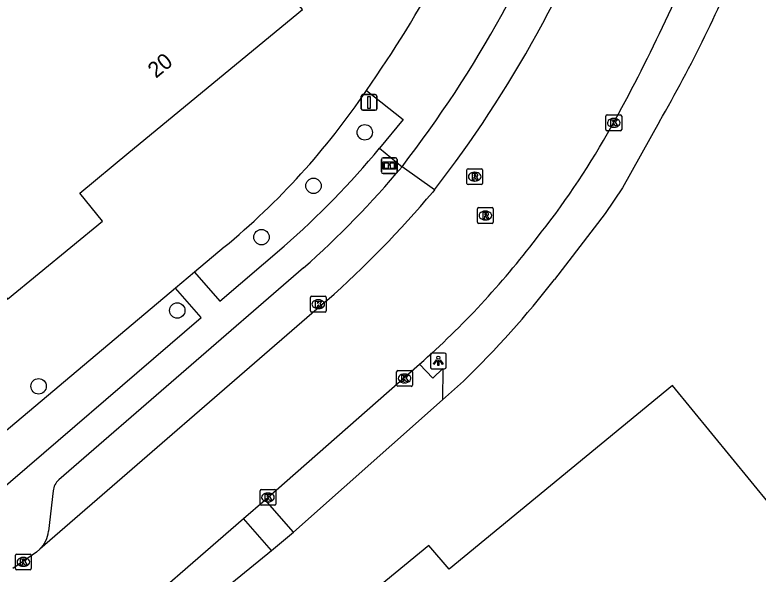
# Model space of a CAD drawing. Extents: x 156651 to 158072, y 387631 to 388990.
# Drawn here: x 157266.5 to 157313.66, y 387776.09 to 387811.56 of the extents above; entities that cross this region are included whole.
import ezdxf

# ---------------------------------------------------------------- set-up
doc = ezdxf.new("R2010")
doc.units = 0
for name, color, linetype in [('IMGEO_Boom', 7, 'Continuous'), ('IMGEO_Groenvoorziening', 7, 'Continuous'), ('IMGEO_Informatiebord', 7, 'Continuous'), ('IMGEO_Kolk', 7, 'Continuous'), ('IMGEO_Lichtpunt', 7, 'Continuous'), ('IMGEO_Pand', 7, 'Continuous'), ('IMGEO_Pand_nummerreeks', 7, 'Continuous'), ('IMGEO_Rijbaan_lokaal_gesloten', 7, 'Continuous'), ('IMGEO_Rioolput', 7, 'Continuous'), ('IMGEO_Verkeersbordpaal', 7, 'Continuous'), ('IMGEO_Voetpad_open', 7, 'Continuous')]:
    doc.layers.add(name, color=color, linetype=linetype)

msp = doc.modelspace()

# ---------------------------------------------------------------- linework, layer by layer
at = {"layer": 'IMGEO_Boom'}
for centre in [(157288.701, 387804.11), (157285.448, 387800.716), (157282.148, 387797.464), (157276.803, 387792.806), (157268.007, 387788.001)]:
    msp.add_circle(centre, 0.489, dxfattribs=at)
at = {"layer": 'IMGEO_Groenvoorziening'}
for points in [[(157279.77, 387796.82), (157277.903, 387795.246)], [(157276.702, 387794.234), (157265.834, 387785.07)], [(157293.629, 387787.152), (157284.18, 387778.754)], [(157273.993, 387770.42), (157282.784, 387777.576)]]:
    msp.add_lwpolyline(points, dxfattribs=at)
msp.add_arc((157249.773, 387833.157), 47.119, 309.5398, 325.9461, dxfattribs=at)
at = {"layer": 'IMGEO_Informatiebord'}
for p, q in [((157289.862, 387802.498), (157290.652, 387802.498)), ((157290.652, 387802.498), (157289.862, 387802.498)), ((157289.762, 387801.598), (157289.762, 387802.398)), ((157289.762, 387802.398), (157289.762, 387801.598)), ((157290.752, 387802.398), (157290.752, 387801.598)), ((157290.752, 387801.598), (157290.752, 387802.398)), ((157290.652, 387801.498), (157289.862, 387801.498)), ((157289.862, 387801.498), (157290.652, 387801.498))]:
    msp.add_line(p, q, dxfattribs=at)
for points in [[(157289.863, 387802.23), (157290.651, 387802.23), (157290.651, 387801.766), (157289.863, 387801.766), (157289.863, 387802.23)], [(157289.928, 387802.165), (157289.928, 387801.831), (157290.203, 387801.831), (157290.204, 387802.044), (157290.308, 387802.045), (157290.309, 387801.831), (157290.586, 387801.831), (157290.586, 387802.165), (157290.31, 387802.165), (157290.31, 387802.085), (157290.204, 387802.085), (157290.204, 387802.165), (157289.928, 387802.165)]]:
    msp.add_lwpolyline(points, dxfattribs=at)
for centre, start, end in [((157289.862, 387802.398), 90, 180), ((157289.862, 387802.398), 90, 180), ((157290.652, 387802.398), 0, 90), ((157290.652, 387802.398), 360, 90), ((157289.862, 387801.598), 180, 270), ((157289.862, 387801.598), 180, 270), ((157290.652, 387801.598), 270, 0), ((157290.652, 387801.598), 270, 0)]:
    msp.add_arc(centre, 0.1, start, end, dxfattribs=at)
at = {"layer": 'IMGEO_Kolk'}
for p, q in [((157303.997, 387804.287), (157303.997, 387805.139)), ((157304.072, 387805.213), (157304.924, 387805.213)), ((157304.485, 387804.993), (157304.51, 387804.993)), ((157304.998, 387805.139), (157304.998, 387804.287)), ((157304.508, 387804.433), (157304.483, 387804.433)), ((157304.924, 387804.213), (157304.072, 387804.213)), ((157285.251, 387792.783), (157285.251, 387793.635)), ((157285.326, 387793.709), (157286.178, 387793.709)), ((157286.252, 387793.635), (157286.252, 387792.783)), ((157285.739, 387793.489), (157285.764, 387793.489)), ((157286.178, 387792.709), (157285.326, 387792.709)), ((157285.762, 387792.929), (157285.737, 387792.929)), ((157290.723, 387788.073), (157290.723, 387788.925)), ((157290.798, 387788.999), (157291.65, 387788.999)), ((157291.724, 387788.925), (157291.724, 387788.073)), ((157291.211, 387788.779), (157291.236, 387788.779)), ((157291.65, 387787.999), (157290.798, 387787.999)), ((157291.234, 387788.219), (157291.209, 387788.219)), ((157282.058, 387780.526), (157282.058, 387781.378)), ((157282.133, 387781.452), (157282.985, 387781.452)), ((157283.059, 387781.378), (157283.059, 387780.526)), ((157282.546, 387781.232), (157282.571, 387781.232)), ((157282.985, 387780.452), (157282.133, 387780.452)), ((157282.569, 387780.672), (157282.544, 387780.672)), ((157266.541, 387776.435), (157266.541, 387777.287)), ((157266.616, 387777.361), (157267.468, 387777.361)), ((157267.029, 387777.141), (157267.054, 387777.141)), ((157267.542, 387777.287), (157267.542, 387776.435)), ((157267.052, 387776.581), (157267.027, 387776.581)), ((157267.468, 387776.361), (157266.616, 387776.361))]:
    msp.add_line(p, q, dxfattribs=at)
for points in [[(157303.997, 387804.287), (157303.997, 387805.139)], [(157304.072, 387805.213), (157304.924, 387805.213)], [(157304.318, 387804.913), (157304.441, 387804.913), (157304.441, 387804.762), (157304.571, 387804.913), (157304.735, 387804.913), (157304.589, 387804.762), (157304.742, 387804.513), (157304.59, 387804.513), (157304.505, 387804.677), (157304.441, 387804.61), (157304.441, 387804.513), (157304.318, 387804.513), (157304.318, 387804.913)], [(157304.998, 387805.139), (157304.998, 387804.287)], [(157304.924, 387804.213), (157304.072, 387804.213)], [(157285.251, 387792.783), (157285.251, 387793.635)], [(157285.326, 387793.709), (157286.178, 387793.709)], [(157286.252, 387793.635), (157286.252, 387792.783)], [(157285.572, 387793.409), (157285.695, 387793.409), (157285.695, 387793.258), (157285.825, 387793.409), (157285.989, 387793.409), (157285.843, 387793.258), (157285.996, 387793.009), (157285.844, 387793.009), (157285.759, 387793.173), (157285.695, 387793.106), (157285.695, 387793.009), (157285.572, 387793.009), (157285.572, 387793.409)], [(157286.178, 387792.709), (157285.326, 387792.709)], [(157290.723, 387788.073), (157290.723, 387788.925)], [(157290.798, 387788.999), (157291.65, 387788.999)], [(157291.724, 387788.925), (157291.724, 387788.073)], [(157291.044, 387788.699), (157291.167, 387788.699), (157291.167, 387788.548), (157291.297, 387788.699), (157291.461, 387788.699), (157291.315, 387788.548), (157291.468, 387788.299), (157291.316, 387788.299), (157291.231, 387788.463), (157291.167, 387788.396), (157291.167, 387788.299), (157291.044, 387788.299), (157291.044, 387788.699)], [(157291.65, 387787.999), (157290.798, 387787.999)], [(157282.058, 387780.526), (157282.058, 387781.378)], [(157282.133, 387781.452), (157282.985, 387781.452)], [(157283.059, 387781.378), (157283.059, 387780.526)], [(157282.379, 387781.152), (157282.502, 387781.152), (157282.502, 387781.001), (157282.632, 387781.152), (157282.796, 387781.152), (157282.65, 387781.001), (157282.803, 387780.752), (157282.651, 387780.752), (157282.566, 387780.916), (157282.502, 387780.849), (157282.502, 387780.752), (157282.379, 387780.752), (157282.379, 387781.152)], [(157282.985, 387780.452), (157282.133, 387780.452)], [(157266.541, 387776.435), (157266.541, 387777.287)], [(157266.616, 387777.361), (157267.468, 387777.361)], [(157266.862, 387777.061), (157266.985, 387777.061), (157266.985, 387776.91), (157267.115, 387777.061), (157267.279, 387777.061), (157267.133, 387776.91), (157267.286, 387776.661), (157267.134, 387776.661), (157267.049, 387776.825), (157266.985, 387776.758), (157266.985, 387776.661), (157266.862, 387776.661), (157266.862, 387777.061)], [(157267.542, 387777.287), (157267.542, 387776.435)], [(157267.468, 387776.361), (157266.616, 387776.361)]]:
    msp.add_lwpolyline(points, dxfattribs=at)
for centre, start, end in [((157304.074, 387805.137), 91.552, 178.448), ((157304.074, 387805.137), 91.552, 178.448), ((157304.922, 387805.137), 1.552, 88.448), ((157304.922, 387805.137), 1.552, 88.448), ((157304.074, 387804.289), 181.552, 268.448), ((157304.074, 387804.289), 181.552, 268.448), ((157304.922, 387804.289), 271.552, 358.448), ((157304.922, 387804.289), 271.552, 358.448), ((157285.328, 387793.633), 91.552, 178.448), ((157285.328, 387793.633), 91.552, 178.448), ((157286.176, 387793.633), 1.552, 88.448), ((157286.176, 387793.633), 1.552, 88.448), ((157285.328, 387792.785), 181.552, 268.448), ((157285.328, 387792.785), 181.552, 268.448), ((157286.176, 387792.785), 271.552, 358.448), ((157286.176, 387792.785), 271.552, 358.448), ((157290.8, 387788.923), 91.552, 178.448), ((157290.8, 387788.923), 91.552, 178.448), ((157291.648, 387788.923), 1.552, 88.448), ((157291.648, 387788.923), 1.552, 88.448), ((157290.8, 387788.075), 181.552, 268.448), ((157290.8, 387788.075), 181.552, 268.448), ((157291.648, 387788.075), 271.552, 358.448), ((157291.648, 387788.075), 271.552, 358.448), ((157282.135, 387781.376), 91.552, 178.448), ((157282.135, 387781.376), 91.552, 178.448), ((157282.983, 387781.376), 1.552, 88.448), ((157282.983, 387781.376), 1.552, 88.448), ((157282.135, 387780.528), 181.552, 268.448), ((157282.135, 387780.528), 181.552, 268.448), ((157282.983, 387780.528), 271.552, 358.448), ((157282.983, 387780.528), 271.552, 358.448), ((157266.618, 387777.285), 91.552, 178.448), ((157266.618, 387777.285), 91.552, 178.448), ((157267.466, 387777.285), 1.552, 88.448), ((157267.466, 387777.285), 1.552, 88.448), ((157266.618, 387776.437), 181.552, 268.448), ((157266.618, 387776.437), 181.552, 268.448), ((157267.466, 387776.437), 271.552, 358.448), ((157267.466, 387776.437), 271.552, 358.448)]:
    msp.add_arc(centre, 0.0765, start, end, dxfattribs=at)
for centre, major_axis, ratio, start_param, end_param in [((157304.484, 387804.713), (-0.387, 0.002), 0.722429, 4.712389, 7.853982), ((157304.509, 387804.713), (-0.39, 0.002), 0.717154, 1.570796, 4.712389), ((157285.738, 387793.209), (-0.387, 0.002), 0.722429, 4.712389, 7.853982), ((157285.763, 387793.209), (-0.39, 0.002), 0.717154, 1.570796, 4.712389), ((157291.21, 387788.499), (-0.387, 0.002), 0.722429, 4.712389, 7.853982), ((157291.235, 387788.499), (-0.39, 0.002), 0.717154, 1.570796, 4.712389), ((157282.545, 387780.952), (-0.387, 0.002), 0.722429, 4.712389, 7.853982), ((157282.57, 387780.952), (-0.39, 0.002), 0.717154, 1.570796, 4.712389), ((157267.028, 387776.861), (-0.387, 0.002), 0.722429, 4.712389, 7.853982), ((157267.053, 387776.861), (-0.39, 0.002), 0.717154, 1.570796, 4.712389)]:
    msp.add_ellipse(centre, major_axis=major_axis, ratio=ratio, start_param=start_param, end_param=end_param, dxfattribs=at)
at = {"layer": 'IMGEO_Lichtpunt'}
for p, q in [((157292.867, 387790.018), (157292.867, 387789.211)), ((157292.867, 387790.018), (157292.867, 387789.211)), ((157293.769, 387790.113), (157292.961, 387790.113)), ((157293.769, 387790.113), (157292.961, 387790.113)), ((157293.863, 387789.211), (157293.863, 387790.018)), ((157293.863, 387789.211), (157293.863, 387790.018)), ((157292.961, 387789.117), (157293.769, 387789.117)), ((157292.961, 387789.117), (157293.769, 387789.117))]:
    msp.add_line(p, q, dxfattribs=at)
for points in [[(157293.241, 387789.682), (157293.28, 387789.654), (157293.092, 387789.392), (157293.054, 387789.419), (157293.241, 387789.682)], [(157293.343, 387789.634), (157293.39, 387789.634), (157293.39, 387789.312), (157293.343, 387789.312), (157293.343, 387789.634)], [(157293.453, 387789.654), (157293.491, 387789.681), (157293.678, 387789.419), (157293.639, 387789.391), (157293.453, 387789.654)]]:
    msp.add_lwpolyline(points, dxfattribs=at)
msp.add_circle((157293.366, 387789.816), 0.0994, dxfattribs=at)
for centre, start, end in [((157292.961, 387790.018), 90, 180), ((157292.961, 387790.018), 90, 180), ((157293.769, 387790.018), 0, 90), ((157293.769, 387790.018), 0, 90), ((157292.961, 387789.211), 180, 270), ((157292.961, 387789.211), 180, 270), ((157293.769, 387789.211), 270, 0), ((157293.769, 387789.211), 270, 360)]:
    msp.add_arc(centre, 0.0946, start, end, dxfattribs=at)
at = {"layer": 'IMGEO_Pand'}
for points in [[(157249.792, 387829.047), (157263.979, 387811.778), (157262.25, 387810.377), (157261.926, 387810.809), (157255.901, 387805.842), (157266.039, 387793.519), (157272.057, 387798.475), (157270.622, 387800.255), (157273.737, 387802.823), (157284.76, 387811.91), (157279.697, 387818.085), (157285.889, 387823.145), (157280.697, 387829.474), (157291.542, 387838.402), (157299.316, 387844.802), (157278.484, 387870.163), (157259.836, 387854.902), (157241.16, 387839.554), (157243.219, 387837.048), (157243.382, 387836.849), (157246.438, 387833.129), (157246.596, 387832.937), (157249.636, 387829.236), (157249.792, 387829.047)], [(157340.665, 387741.338), (157344.144, 387744.224), (157339.41, 387750), (157308.228, 387788.046), (157294.05, 387776.396), (157292.77, 387777.908), (157288.491, 387774.397), (157289.551, 387773.149), (157287.377, 387771.317), (157286.246, 387772.551), (157280.605, 387767.928), (157290.591, 387755.753), (157292.107, 387757.007), (157297.863, 387750), (157319.262, 387723.952), (157319.361, 387723.831)]]:
    msp.add_lwpolyline(points, dxfattribs=at)
at = {"layer": 'IMGEO_Rijbaan_lokaal_gesloten'}
for points in [[(157304.091, 387804.034), (157304.594, 387804.903)], [(157293.119, 387800.457), (157293.014, 387800.321)], [(157286.301, 387793.452), (157268.085, 387777.663)], [(157282.385, 387780.806), (157292.183, 387789.406)], [(157281.01, 387779.609), (157282.385, 387780.806)], [(157272.493, 387772.206), (157281.01, 387779.609)], [(157268.085, 387777.663), (157267.868, 387777.475), (157266.365, 387776.435)]]:
    msp.add_lwpolyline(points, dxfattribs=at)
for centre, radius, start, end in [((157231.904, 387847.749), 77.355, 322.31186, 339.92433), ((157200.407, 387861.75), 118.687, 331.382, 338.18195), ((157260.794, 387828.461), 49.712, 321.2921, 330.5688), ((157244.168, 387841.343), 63.786, 311.34034, 319.97578), ((157255.479, 387830.935), 55.424, 311.4701, 322.7324)]:
    msp.add_arc(centre, radius, start, end, dxfattribs=at)
at = {"layer": 'IMGEO_Rioolput'}
for p, q in [((157295.176, 387800.874), (157295.176, 387801.726)), ((157295.251, 387801.8), (157296.103, 387801.8)), ((157295.664, 387801.58), (157295.689, 387801.58)), ((157296.177, 387801.726), (157296.177, 387800.874)), ((157296.103, 387800.8), (157295.251, 387800.8)), ((157295.687, 387801.02), (157295.662, 387801.02)), ((157295.852, 387798.409), (157295.852, 387799.261)), ((157295.927, 387799.335), (157296.779, 387799.335)), ((157296.853, 387799.261), (157296.853, 387798.409)), ((157296.34, 387799.115), (157296.365, 387799.115)), ((157296.779, 387798.335), (157295.927, 387798.335)), ((157296.363, 387798.555), (157296.338, 387798.555))]:
    msp.add_line(p, q, dxfattribs=at)
for points in [[(157295.176, 387800.874), (157295.176, 387801.726)], [(157295.251, 387801.8), (157296.103, 387801.8)], [(157296.177, 387801.726), (157296.177, 387800.874)], [(157295.765, 387801.498), (157295.513, 387801.5), (157295.513, 387801.1)], [(157295.513, 387801.1), (157295.637, 387801.1), (157295.637, 387801.262), (157295.648, 387801.262)], [(157295.691, 387801.419), (157295.637, 387801.419), (157295.637, 387801.338)], [(157295.637, 387801.338), (157295.689, 387801.338)], [(157295.695, 387801.233), (157295.766, 387801.1), (157295.906, 387801.1), (157295.841, 387801.226)], [(157296.103, 387800.8), (157295.251, 387800.8)], [(157295.852, 387798.409), (157295.852, 387799.261)], [(157295.927, 387799.335), (157296.779, 387799.335)], [(157296.853, 387799.261), (157296.853, 387798.409)], [(157296.441, 387799.033), (157296.189, 387799.035), (157296.189, 387798.635)], [(157296.189, 387798.635), (157296.313, 387798.635), (157296.313, 387798.797), (157296.324, 387798.797)], [(157296.367, 387798.954), (157296.313, 387798.954), (157296.313, 387798.873)], [(157296.313, 387798.873), (157296.365, 387798.873)], [(157296.371, 387798.768), (157296.442, 387798.635), (157296.582, 387798.635), (157296.517, 387798.761)], [(157296.779, 387798.335), (157295.927, 387798.335)]]:
    msp.add_lwpolyline(points, dxfattribs=at)
for centre, radius, start, end in [((157295.253, 387801.724), 0.0765, 91.552, 178.448), ((157295.253, 387801.724), 0.0765, 91.552, 178.448), ((157296.101, 387801.724), 0.0765, 1.552, 88.448), ((157296.101, 387801.724), 0.0765, 1.552, 88.448), ((157295.647, 387801.209), 0.0533, 26.0293, 88.6989), ((157295.673, 387801.527), 0.19, 274.7715, 282.9687), ((157295.697, 387801.323), 0.0964, 77.0061, 93.1865), ((157295.711, 387801.38), 0.0378, 276.6634, 79.6772), ((157295.764, 387801.388), 0.109, 350.3612, 89.416), ((157295.762, 387801.388), 0.112, 277.5842, 350.9817), ((157295.746, 387801.173), 0.108, 29.5134, 73.7905), ((157295.253, 387800.876), 0.0765, 181.552, 268.448), ((157295.253, 387800.876), 0.0765, 181.552, 268.448), ((157296.101, 387800.876), 0.0765, 271.552, 358.448), ((157296.101, 387800.876), 0.0765, 271.552, 358.448), ((157295.929, 387799.259), 0.0765, 91.552, 178.448), ((157295.929, 387799.259), 0.0765, 91.552, 178.448), ((157296.777, 387799.259), 0.0765, 1.552, 88.448), ((157296.777, 387799.259), 0.0765, 1.552, 88.448), ((157296.323, 387798.744), 0.0533, 26.0293, 88.6989), ((157296.349, 387799.062), 0.19, 274.7715, 282.9687), ((157296.373, 387798.858), 0.0964, 77.0061, 93.1865), ((157296.387, 387798.915), 0.0378, 276.6634, 79.6772), ((157296.44, 387798.923), 0.109, 350.3612, 89.416), ((157296.438, 387798.923), 0.112, 277.5842, 350.9817), ((157296.422, 387798.708), 0.108, 29.5134, 73.7905), ((157295.929, 387798.411), 0.0765, 181.552, 268.448), ((157295.929, 387798.411), 0.0765, 181.552, 268.448), ((157296.777, 387798.411), 0.0765, 271.552, 358.448), ((157296.777, 387798.411), 0.0765, 271.552, 358.448)]:
    msp.add_arc(centre, radius, start, end, dxfattribs=at)
for centre, major_axis, ratio, start_param, end_param in [((157295.663, 387801.3), (-0.387, 0.002), 0.722429, 4.712389, 7.853982), ((157295.688, 387801.3), (-0.39, 0.002), 0.717154, 1.570796, 4.712389), ((157296.339, 387798.835), (-0.387, 0.002), 0.722429, 4.712389, 7.853982), ((157296.364, 387798.835), (-0.39, 0.002), 0.717154, 1.570796, 4.712389)]:
    msp.add_ellipse(centre, major_axis=major_axis, ratio=ratio, start_param=start_param, end_param=end_param, dxfattribs=at)
at = {"layer": 'IMGEO_Verkeersbordpaal'}
for p, q in [((157288.475, 387805.607), (157288.475, 387806.407)), ((157288.475, 387806.407), (157288.475, 387805.607)), ((157288.575, 387806.507), (157289.365, 387806.507)), ((157289.365, 387806.507), (157288.575, 387806.507)), ((157289.465, 387806.407), (157289.465, 387805.607)), ((157289.465, 387805.607), (157289.465, 387806.407)), ((157289.365, 387805.507), (157288.575, 387805.507)), ((157288.575, 387805.507), (157289.365, 387805.507))]:
    msp.add_line(p, q, dxfattribs=at)
msp.add_lwpolyline([(157288.895, 387806.382), (157289.045, 387806.382), (157289.045, 387805.632), (157288.895, 387805.632), (157288.895, 387806.382)], dxfattribs=at)
for centre, start, end in [((157288.575, 387806.407), 90, 180), ((157288.575, 387806.407), 90, 180), ((157289.365, 387806.407), 0, 90), ((157289.365, 387806.407), 360, 90), ((157288.575, 387805.607), 180, 270), ((157288.575, 387805.607), 180, 270), ((157289.365, 387805.607), 270, 0), ((157289.365, 387805.607), 270, 0)]:
    msp.add_arc(centre, 0.1, start, end, dxfattribs=at)
at = {"layer": 'IMGEO_Voetpad_open'}
for points in [[(157288.812, 387806.772), (157291.142, 387804.921), (157289.642, 387803.1)], [(157307.397, 387804.794), (157305.043, 387800.595), (157303.942, 387798.962), (157300.737, 387794.775)], [(157289.642, 387803.1), (157291.063, 387801.929)], [(157293.119, 387800.457), (157291.063, 387801.929)], [(157277.903, 387795.246), (157279.511, 387793.395), (157283.578, 387796.887)], [(157284.808, 387795.507), (157269.292, 387782.069)], [(157277.903, 387795.246), (157276.702, 387794.234)], [(157264.231, 387780.276), (157278.319, 387792.372), (157276.702, 387794.234)], [(157292.183, 387789.406), (157293.018, 387788.525), (157293.651, 387789.12), (157293.629, 387787.152)], [(157294.955, 387788.331), (157293.629, 387787.152)], [(157268.934, 387781.372), (157268.643, 387778.81)], [(157284.18, 387778.754), (157282.385, 387780.806)], [(157282.784, 387777.576), (157281.01, 387779.609)], [(157282.784, 387777.576), (157284.18, 387778.754)]]:
    msp.add_lwpolyline(points, dxfattribs=at)
for centre, radius, start, end in [((157227.9, 387849.467), 74.385, 324.97213, 338.9217), ((157231.182, 387848.181), 75.663, 322.31758, 339.85782), ((157232.637, 387848.1), 86.397, 329.91795, 338.04808), ((157247.514, 387838.152), 54.803, 311.1522, 320.2384), ((157245.148, 387840.393), 59.897, 311.46298, 320.0465), ((157253.544, 387831.304), 59.679, 313.9397, 322.25903), ((157269.969, 387781.281), 1.039, 130.6579, 174.9693), ((157266.698, 387779.047), 1.96, 315.0676, 353.0478)]:
    msp.add_arc(centre, radius, start, end, dxfattribs=at)

# ---------------------------------------------------------------- texts
at = {"layer": 'IMGEO_Pand_nummerreeks'}
msp.add_text('20', height=1, rotation=39.4997, dxfattribs=at).set_placement((157275.452, 387807.503))

doc.saveas('drawing.dxf')
